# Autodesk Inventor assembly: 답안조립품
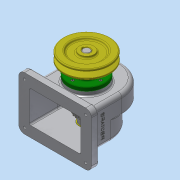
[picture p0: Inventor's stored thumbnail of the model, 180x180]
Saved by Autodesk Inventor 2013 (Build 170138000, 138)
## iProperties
Created: 2017-11
Part Number: 답안조립품
Document SubType Name: Assembly
Designer: Administrator
Author: Administrator
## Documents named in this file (14)
- C:\Users\Administrator\Desktop\471108V1023\답안조립품.iam
- C:\Users\Administrator\Desktop\471108V1023\V-벨트풀리.ipt
- C:\Users\Administrator\Desktop\471108V1023\뒤커버.ipt
- C:\Users\Administrator\Desktop\471108V1023\멈춤나사 - M4 x 10.ipt
- 멈춤나사 - M4 x 10.ipt
- C:\Users\Administrator\Desktop\471108V1023\베어링 6002.ipt
- C:\Users\Administrator\Desktop\471108V1023\본체.ipt
- C:\Users\Administrator\Desktop\471108V1023\볼트 M3 x 8.ipt
- C:\Users\Administrator\Desktop\471108V1023\스퍼기어.ipt
- C:\Users\Administrator\Desktop\471108V1023\앞커버.ipt
- C:\Users\Administrator\Desktop\471108V1023\오일 실 15 30 7.ipt
- C:\Users\Administrator\Desktop\471108V1023\축.ipt
- C:\Users\Administrator\Desktop\471108V1023\키 - 5 x 5 x 18.ipt
- C:\Users\Administrator\Desktop\471108V1023\키 - 6 x 6 x 22.ipt
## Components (1 placed, 1 different names)
1. V-벨트풀리:1 — 플러쉬:1
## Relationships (1: Flush 1)
- 플러쉬:1 [Flush]: V-벨트풀리:1
